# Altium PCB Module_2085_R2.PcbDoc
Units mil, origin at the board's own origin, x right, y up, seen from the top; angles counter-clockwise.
Board outline 6000 x 4000 mil, 2 copper layers (Top Layer, Bottom Layer); 61 components, 40 nets, 171 pads, 11 vias.
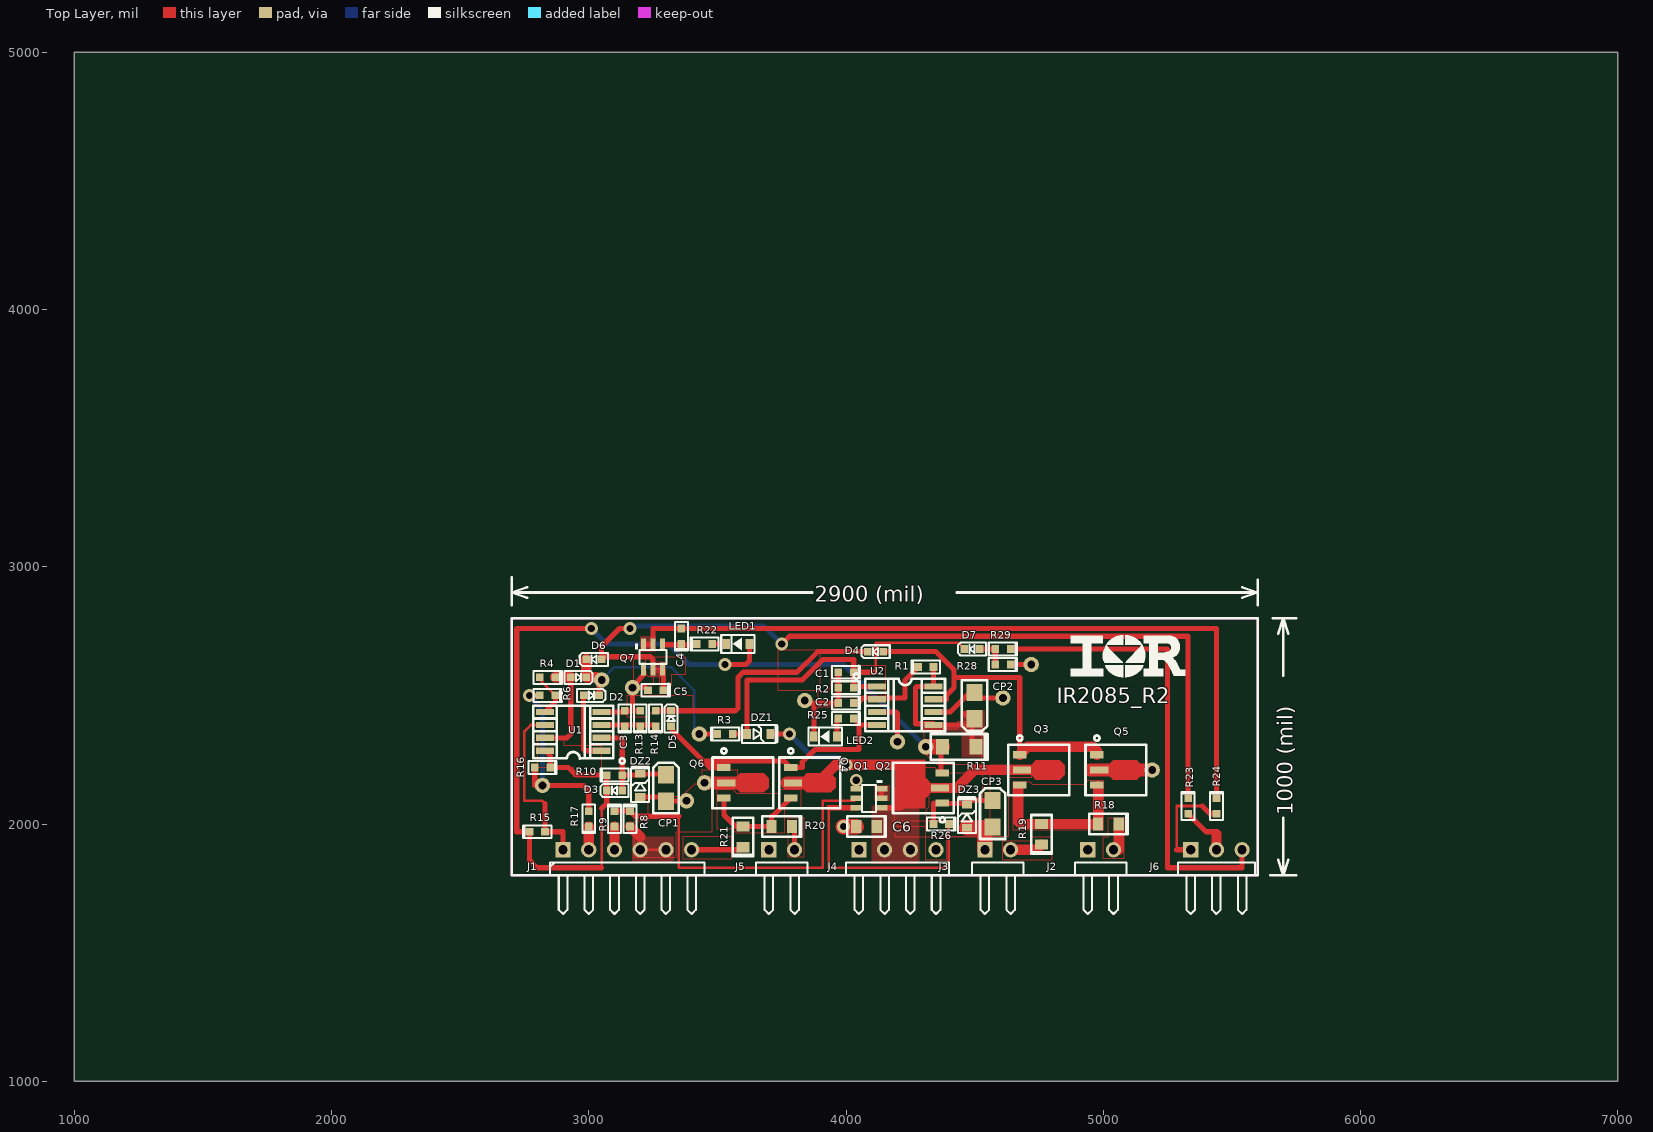
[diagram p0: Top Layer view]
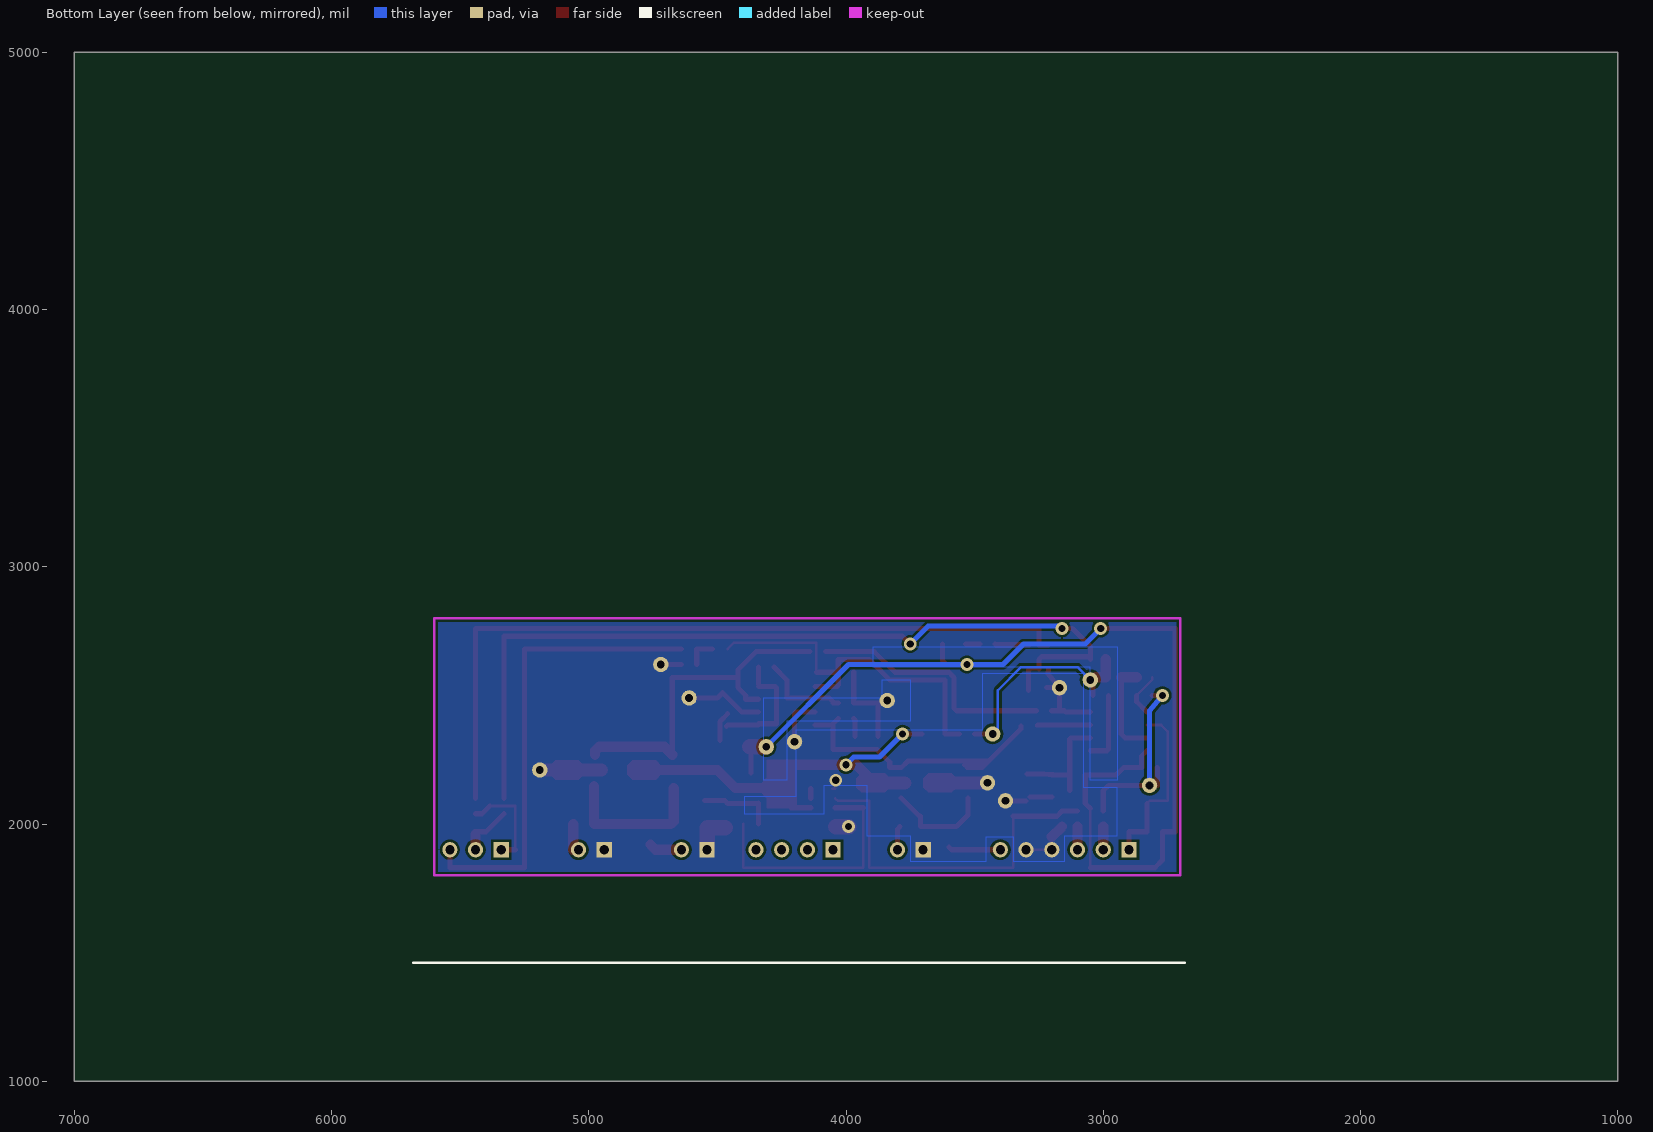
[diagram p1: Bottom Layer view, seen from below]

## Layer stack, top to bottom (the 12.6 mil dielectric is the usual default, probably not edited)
Top Layer: signal copper 1.4
Dielectric: dielectric 12.6, FR-4, Dk 4.8
Bottom Layer: signal copper 1.4

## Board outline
1000,1000 7000,1000 7000,5000 1000,5000

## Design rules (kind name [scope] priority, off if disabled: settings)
Clearance [All] p1: gap=10
ComponentClearance [All] p1: gap=10 collisioncheckmode=3 verticalgap=10
PlaneConnect [All] p1: planeconnectstyle=Direct reliefexpansion=20 reliefentries=4 reliefconductorwidth=10 reliefairgap=10
PolygonConnect [All] p1: connectstyle=Direct reliefconductorwidth=10 reliefentries=4 polygonreliefangle="90 Angle"
RoutingVias [All] p1: holewidth=28 width=40 viastyle="Through Hole" minholewidth=28 minwidth=38 maxholewidth=28 maxwidth=50
SolderMaskExpansion [All] p1: expansion=4
TestPointUsage [All] p1: valid=0 allowmultiple=FALSE
Testpoint [All] p1: side=15 testpointundercomponent=TRUE minsize=40 maxsize=100 preferedsize=60 minholesize=0 maxholesize=40 preferedholesize=32 testpointgrid=1 style=1023 order=0-112345678
Width [All] p1: maxlimit=40 minlimit=10 preferedwidth=20
17 further rules are at their usual default settings.

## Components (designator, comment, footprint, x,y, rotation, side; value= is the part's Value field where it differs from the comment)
C1 "C-603" C-603 4000,2590 r270 top
C2 "C-603" C-603 4000,2470 r270 top
C3 "C-603" C-603 3140,2410 r180 top
C4 "C-603" C-603 3360,2730 r180 top
C5 "C-603" C-603 3260,2520 r270 top
C6 "C-805" C-805 4080,1990 r270 top
CP1 "C-TAN-A" C-TAN-A 3300,2140 r0 top
CP2 "C-TAN-A" C-TAN-a 4500,2460 r180 top
CP3 "C-TAN-A" C-TAN-a 4570,2040 r0 top
D1 "SOD323_D" SOD523_D 2960,2570 r0 top
D2 "SOD323_D" SOD523_D 3010,2500 r0 top
D3 "SOD323_D" SOD523_D 3100,2130 r180 top
D4 "SOD323_D" SOD523_D 4115,2670 r180 top
D5 "SOD323_D" SOD523_D 3320,2410 r90 top
D6 "SOD323_D" SOD523_D 3020,2640 r180 top
D7 "SOD323_D" SOD523_D 4490,2680 r180 top
DZ1 "SOD123_Z" SOD323_Z 3660,2350 r180 top
DZ2 "SOD123_Z" SOD323_Z 3200,2150 r270 top
DZ3 "SOD123_Z" SOD323_Z 4470,2030 r270 top
J1 "Header 6H" HDR1X6H 2900,1900 r0 top locked
J2 "Header 2" HDR1X2H 4940,1900 r0 top
J3 "Header 2" HDR1X2H 4540,1900 r0 top
J4 "Header 4H" HDR1X4H 4050,1900 r0 top locked
J5 "Header 2" HDR1X2H 3700,1900 r0 top locked
J6 "Header 3H" HDR1X3H 5340,1900 r0 top
LED1 "LED-805" LED-805 3580,2700 r0 top
LED2 "LED-805" LED-805 3920,2340 r0 top
Q1 "XN4311" XN04311_XN04311(Primary) 4090,2100 r0 top
Q2 "PBSS305NX" SOT89 4320,2140 r90 top
Q3 "PBSS305NX" SOT89 4730,2210 r270 top
Q4 "PBSS305NX" SOT89 3840,2160 r270 top
Q5 "PBSS305PX" SOT89 5030,2210 r270 top
Q6 "PBSS305PX" SOT89 3580,2160 r270 top
Q7 "XN4311" XN04311_XN04311(Primary) 3250,2650 r90 top
R1 "R-603" R-603 4310,2610 r180 top
R2 "R-603" R-603 4000,2530 r0 top
R3 "R-603" R-603 3530,2350 r180 top
R4 "R-603" R-603 2840,2570 r0 top
R6 "R-603" R-603 2840,2500 r0 top
R8 "R-603" R-603 3160,2020 r90 top
R9 "R-603" R-603 3100,2020 r90 top
R10 "R-603" R-603 3100,2190 r180 top
R11 "R-1206" R-1206 4440,2300 r0 top
R13 "R-603" R-603 3200,2410 r270 top
R14 "R-603" R-603 3260,2410 r270 top
R15 "R-603" R-603 2800,1970 r180 top
R16 "R-603" R-603 2820,2220 r0 top
R17 "R-603" R-603 3000,2020 r270 top
R18 "R-805" R-805 5020,2000 r180 top
R19 "R-805" R-805 4760,1960 r90 top
R20 "R-805" R-805 3750,1990 r180 top
R21 "R-805" R-805 3600,1950 r90 top
R22 "R-603" R-603 3450,2700 r180 top
R23 "R-603" R-603 5330,2070 r90 top
R24 "R-603" R-603 5440,2070 r90 top
R25 "R-603" R-603 4000,2410 r0 top
R26 "R-603" R-603 4370,2000 r0 top
R28 "R-603" R-603 4610,2620 r0 top
R29 "R-603" R-603 4610,2680 r0 top
U1 "TLC082" SO8 2940,2360 r180 top
U2 "IR2086" SO8 4230,2460 r0 top

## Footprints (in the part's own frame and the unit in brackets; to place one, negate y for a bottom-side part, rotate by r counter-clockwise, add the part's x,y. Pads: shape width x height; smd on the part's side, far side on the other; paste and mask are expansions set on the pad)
C-603 [mil]
  rect 30x30 smd: 1(0,30) 2(0,-30)
  silkscreen extent -25,-55 25,55
C-805 [mil]
  rect 50x40 smd: 1(0,40) 2(0,-40)
  silkscreen extent -40,-75 40,75
C-TAN-A [mm]
  rect 1.6x1.7 smd: 1(0,1.3) 2(0,-1.3)
  silkscreen extent -1.25,-2.5 1.25,2.5
C-TAN-a [mm]
  rect 1.6x1.7 smd: 1(0,1.3) 2(0,-1.3)
  silkscreen extent -1.25,-2.5 1.25,2.5
HDR1X2H [mm] "Connector; Header; 2 Position; Right Angle"
  rect 1.5x1.5 hole 0.9: 1(0,0)
  round 1.5 hole 0.9: 2(2.54,0)
  silkscreen extent -1.27,-6.35 3.81,-1.27
HDR1X3H [mm] "Connector; Header; 3 Position; Right Angle"
  rect 1.5x1.5 hole 0.9: 1(0,0)
  round 1.5 hole 0.9: 2(2.54,0) 3(5.08,0)
  silkscreen extent -1.27,-6.35 6.35,-1.27
HDR1X4H [mm] "Connector; Header; 4 Position; Right Angle"
  rect 1.5x1.5 hole 0.9: 1(0,0)
  round 1.5 hole 0.9: 2(2.54,0) 3(5.08,0) 4(7.62,0)
  silkscreen extent -1.27,-6.35 8.89,-1.27
HDR1X6H [mm] "Connector; Header; 6 Position; Right Angle"
  rect 1.5x1.5 hole 0.9: 1(0,0)
  round 1.5 hole 0.9: 2(2.54,0) 3(5.08,0) 4(7.62,0) 5(10.16,0) 6(12.7,0)
  silkscreen extent -1.27,-6.35 13.97,-1.27
LED-805 [mil]
  rect 30x40 smd: 1(-45,0) 2(45,0)
  silkscreen extent -65,-35 65,35
R-603 [mil]
  rect 30x30 smd: 1(30,0) 2(-30,0)
  silkscreen extent -55,-25 55,25
R-805 [mil]
  rect 40x50 smd: 1(-40,0) 2(40,0)
  silkscreen extent -75,-40 75,40
R-1206 [mil]
  rect 50x60 smd: 1(65,0) 2(-65,0)
  silkscreen extent -110,-50 110,50
SO8 [mil]
  rect 70x24 smd: 1(-110,75) 2(-110,25) 3(-110,-25) 4(-110,-75) 5(110,-75) 6(110,-25) 7(110,25) 8(110,75)
  silkscreen extent -200,-100 155,125
SOD323_Z [mil]
  rect 30x40 smd: 1(-45,0) 2(45,0)
  silkscreen extent -70,-35 65,35
SOD523_D [mil]
  rect 30x30 smd: 1(30,0) 2(-30,0)
  silkscreen extent -55,-25 55,25
SOT89 [mm]
  rect 0.7x1.35 smd: 1(-1.5,-1.388) 3(1.5,-1.388)
  rect 0.7x1.8 smd: 2(0,-1.162)
  round 0 smd paste-25.4 mask-25.4: 4(0,1.388)
  Top Layer region: 0.475,3.037 0.95,2.562 0.95,0.213 0.475,-0.262 -0.475,-0.262 -0.95,0.213 -0.95,2.562 -0.475,3.037
  silkscreen extent -3.4,-2.51 2.5,3.49
XN04311_XN04311(Primary) [mil]
  rect 50x20 smd: 1(47,37) 2(47,0) 3(47,-37) 4(-48,-37) 5(-48,0) 6(-48,37)
  silkscreen extent -28,-53 50,70

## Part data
CP1 CP2 CP3: library part C-TAN-B, "C-TAN-B"
D7: "DIODE SWITCH 100V 150MW SOD-523"
DZ3: "DIODE ZENER 200MW 12V SOD323"
J1 J4 J6: library part "Header 2", "Header, 2-Pin"
J2 J3 J5: "Header, 2-Pin"
LED2: "LED 468NM BLUE CLEAR 0805 SMD"
Q2 Q3 Q4: library part SOT89-NPN, "SOT89-NPN"
Q5 Q6: library part SOT89-PNP, "SOT89-PNP"
R22: library part R-805, "R-805"
R25: "RES 4.7K OHM 1/10W 5% 0603 SMD"
R26 R28: "RES 1.0K OHM 1/10W 5% 0603 SMD"
R29: "RES 56K OHM 1/10W 5% 0603 SMD"
U1: library part LM833
U2: library part IR2085

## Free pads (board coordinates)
  round 60 hole 30: 4(2820,2150) 7(5190,2210) 9(3380,2090) 10(3450,2160) 11(3840,2480) 12(4200,2320) 13(4720,2620) 14(4610,2490) 15(3170,2530) 16(3050,2560) 18(4310,2300) 20(3430,2350)

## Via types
v1: diameter 50, hole 28, Top Layer to Bottom Layer, 11 vias

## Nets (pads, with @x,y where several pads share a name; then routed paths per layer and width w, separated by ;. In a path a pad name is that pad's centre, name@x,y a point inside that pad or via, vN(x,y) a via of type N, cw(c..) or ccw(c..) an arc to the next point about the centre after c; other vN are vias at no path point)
14.4V: DZ1.1 J4.2 J4.3 Q1.3 Q2.2 Q3.2 Q4.2 | length 1510.8
  Top Layer w20: DZ1.1 v1(3780,2350) ; Q1.3 4213,2063 4230,2080 4227,2083
  Top Layer w40: 3894.63,2164.63 3960,2230 4250,2230 ; 4250,2140 4290,2140 4430,2140 4500,2210 4750,2210
  Top Layer w50: Q4.2@3770,2160 3920.39,2160
  Bottom Layer w20: v1(3780,2350) 3870,2260 3970,2260 v1(4000,2230)
CS: C1.1 D7.1 DZ1.2 R2.1 R3.2 U2.1 | length 1458.5
  Top Layer w10: 4115,2590 4115,2705 4435,2705 D7.1
  Top Layer w20: R3.2 DZ1.2 3615,2557.93 ; 3615,2560 3830,2560 3910,2640 4030,2640 4030,2540 4035,2535 U2.1 ; C1.1 4115,2590
GND: C1.2 C2.2 C3.2 C5.2 C6.2 CP1.2 CP2.2 CP3.2 DZ2.2 DZ3.2 J1.4 J1.5 J2.1 J3.1 J5.1 LED2.1 pad.7 pad.9 pad.10 pad.11 pad.12 pad.13 pad.14 pad.15 Q1.6 Q5.2 Q6.2 Q7.6 R2.2 R8.2 R13.2 R28.1 U1.4 U2.3 U2.6 | length 2426.3
  Top Layer w10: 3200,1950 J1.4 J1.5 ; v1@4030,2160 4053,2137 Q1.6
  Top Layer w20: U1.4 3145,2435 3150,2440 R13.2 ; 3170,2440 pad.15 ; DZ2.2 CP1.2@3283.82,2105 ; Q7.6 3214.72,2584.35 pad.15 ; C5.2@3220,2530 pad.15 ; CP1.2 3301.18,2090 pad.9 ; pad.11 3850,2470 C2.2 C1.2 ; LED2.1 3875,2470 ; U2.3 4195,2435 4200,2430 pad.12 ; U2.6 4405,2435 CP2.2@4480,2510 ; CP2.2@4480,2511.18 CP2.2@4480,2510 ; pad.14 4500,2490 CP2.2@4480,2510 ; R28.1 pad.13
  Top Layer w40: R8.2 3200,1950
  Top Layer w50: pad.10 3670,2160 ; Q5.2@4950,2210 pad.7
  Top Layer w60: v1(3990,1990) C6.2 ; DZ3.2 4540,1985 J3.1
  other v1: 4040,2170
LO1: D5.2 Q4.1 Q6.1 R25.1 U2.4 | length 1220.5
  Top Layer w20: D5.2 3320,2370 3470,2220 Q6.1@3530,2220 ; 3450,2245.37 3759.06,2245.37 Q4.1 3830,2219.06 3830,2240 3880,2290 4050,2290 4050,2380 ; 3470,2240 3480,2230 Q6.1@3540,2230 ; 3500,2245.37 3502.69,2242.69 ; 3502.69,2241.74 Q6.1@3514.43,2230 ; Q6.1 Q6.1@3525.37,2220 ; R25.1 4055,2385 U2.4
NetC2_1: C2.1 R1.1 U2.2 | length 341.9
  Top Layer w20: C2.1 4050,2470 ; 4050,2475 4065,2490 4230,2490 4230,2555 ; 4230,2560 R1.1
NetC3_1: C3.1 R13.1 R14.1 U1.3 | length 212.1
  Top Layer w10: R14.1@3255,2385 R14.1
  Top Layer w20: U1.3 R14.1@3255,2385
NetC4_1: C4.1 Q7.3 R22.1 | length 134.2
  Top Layer w20: Q7.3 3417,2697 R22.1
NetCP1_1: CP1.1 D3.2 DZ2.1 R10.2 U1.2 | length 449
  Top Layer w20: U1.2 3125,2335 3130,2330 R10.2 ; D3.2 R10.2 ; CP1.1@3296.18,2195 3230,2195 3200.38,2191.66 3196.18,2191.18 3195,2190 R10.2
NetCP3_1: CP3.1 DZ3.1 Q2.1 R26.2 | length 310
  Top Layer w20: R26.2 4340,2080.78 Q2.1@4374.61,2080.23 ; Q2.1@4360,2080 4374.64,2080.23 4460.23,2080.23 4471.18,2091.18 CP3.1@4550,2091.18
NetD1_1: D1.1 D2.1 D6.1 pad.16 pad.20 R3.1 | length 850.4
  Top Layer w10: pad.16@3030,2570 pad.16@3040,2560
  Top Layer w20: D2.1 pad.16@3040,2560 ; v1(3430,2350) R3.1
  Top Layer w40: D6.1 D1.1 pad.16@3030,2570
  Bottom Layer w10: pad.16 3100,2610 3320,2610 3410,2520 3410,2370 v1(3430,2350)
NetD1_2: D1.2 R4.1 U1.7 | length 386.2
  Top Layer w20: U1.7 2915,2335 2930,2350 D1.2
  Top Layer w40: R4.1 D1.2
NetD2_2: D2.2 U1.1 | length 282.1
  Top Layer w10: 2980,2290 2985,2285
  Top Layer w20: 2980,2290 D2.2 ; 2985,2285 U1.1
NetD4_1: D4.1 D5.1 R14.2 | length 985.6
  Top Layer w20: R14.2 D5.1 3570,2440 3580,2450 3580,2570 3600,2590 3810,2590 3890,2670 D4.1@4080,2670
NetD4_2: D4.2 Q3.1 Q5.1 U2.7 | length 1377.5
  Top Layer w20: D4.2@4140,2670 4350,2670 4420,2600 4420,2570 ; U2.7 4390,2485 4390,2500 4420,2530 4420,2570 ; Q3.1 4675.37,2570 4420,2570
  Top Layer w40: Q3.1 4706.32,2300 4960,2300 4975.37,2284.63 Q5.1
NetJ1_1: J1.1 R15.2 U1.6 | length 694.5
  Top Layer w10: 2830,2080 2820,2090 2750,2090 2750,2360 2775,2385 U1.6
  Top Layer w20: 2830,2080 R15.2 2900,1970 J1.1
NetJ1_2: J1.2 R17.1 | length 90
  Top Layer w40: J1.2 R17.1
NetJ1_6: J1.6 R21.1 | length 204.1
  Top Layer w20: J1.6 3590,1900 R21.1
NetJ2_2: J2.2 R18.1 | length 120
  Top Layer w40: J2.2 5060,1900 R18.1
NetJ3_2: J3.2 R19.1 | length 138.3
  Top Layer w40: J3.2@4630,1900 4740,1900 R19.1
NetJ5_2: J5.2 R20.1 | length 94.1
  Top Layer w20: R20.1 3800,1980 J5.2
NetJ6_1: J6.1 R24.2 | length 392.4
  Top Layer w10: 5285,1900 5285,2070 5385,2070
  Top Layer w20: 5285,1900 J6.1 ; 5385,2070 5415,2040 R24.2
NetJ6_2: J6.2 R23.2 | length 203.1
  Top Layer w20: R23.2 5400,1970 5430,1970 5440,1960
  Top Layer w40: J6.2 5440,1960
NetJ6_3: J6.3 R29.1 | length 1820
  Top Layer w20: R29.1 5250,2680 5250,1830 5540,1830 J6.3
NetLED1_1: LED1.1 R22.2 | length 55
  Top Layer w20: R22.2 LED1.1
NetLED2_2: LED2.2 R25.2 | length 72.1
  Top Layer w20: LED2.2 3965,2405 R25.2
NetQ1_1: Q1.1 Q1.2 | length 37
  Top Layer w20: Q1.2 Q1.1
NetQ1_4: Q1.4 R26.1 | length 979
  Top Layer w10: 3933,2063 3933,1830 4400,1830 R26.1
  Top Layer w20: 3933,2063 Q1.4
NetQ1_5: Q1.5 R8.1 R9.1 | length 1414.4
  Top Layer w10: 3350,2030 3350,1830 3910,1830 3910,2090 4032,2090 Q1.5
  Top Layer w20: R9.1 R8.1 3180,2030 3350,2030
NetQ3_3: Q3.3 Q5.3 R18.2 R19.2 | length 590.5
  Top Layer w40: Q3.3@4670,2140 4670,2010 4680,2000 R18.2 Q5.3@4980,2146.32
NetQ4_3: Q4.3 Q6.3 R20.2 R21.2 | length 414.2
  Top Layer w20: Q6.3 3525.37,2034.63 3570,1990 R20.2 3710,2030 3714.43,2030 Q4.3
NetR4_2: R4.2 R6.1 U1.5 | length 176.4
  Top Layer w10: R4.2 2810,2560 R6.1
  Top Layer w20: U1.5 2870,2475 R6.1
NetR6_2: pad.4 R6.2 R16.2 R17.2 | length 776.4
  Top Layer w20: v1(2770,2500) R6.2 ; R16.2 2790,2150 2980,2150 3000,2130 R17.2
  Bottom Layer w20: v1(2770,2500) 2820,2440 pad.4
OVP2: D7.2 R28.2 R29.2 | length 120
  Top Layer w20: D7.2 R29.2 R28.2
"REMOTE ON": J1.3 R9.2 | length 90
  Top Layer w40: J1.3 R9.2
SCP+: C5.1 D6.2 Q7.4 Q7.5 R23.1 | length 3396.9
  Top Layer w10: Q7.5 Q7.4
  Top Layer w20: D6.2 3050,2690 3120,2760 v1(3160,2760) ; D6.2@3050,2650 3240,2650 3250,2640 Q7.5 ; Q7.4 3290,2599 C5.1 ; v1(3750,2700) 3780,2730 5330,2730 R23.1
  Bottom Layer w20: v1(3160,2760) 3170,2770 3680,2770 v1(3750,2700)
SCP-: C4.2 Q7.1 Q7.2 R24.1 | length 2950
  Top Layer w20: Q7.1 Q7.2 3250,2760 C4.2 5440,2760 R24.1
TURN_ON: D3.1 LED1.2 pad.18 Q2.3 R10.1 R11.2 R15.1 R16.1 U1.8 | length 4029.1
  Top Layer w10: 3050,1830 3050,2060
  Top Layer w20: U1.8 2850,2265 R16.1 2920,2220 2950,2190 R10.1 D3.1 3070,2080 3050,2060 ; v1(3010,2760) 2720,2760 2720,1970 R15.1 2770,1860 2800,1830 3050,1830 ; v1(3530,2620) 3610,2620 3625,2635 LED1.2 ; Q2.3@4370,2199.06 R11.2@4370,2300
  Top Layer w60: v1(4310,2300) R11.2
  Bottom Layer w20: v1(3010,2760) 3070,2700 3310,2700 3390,2620 3990,2620 v1(4310,2300)
VCC: CP2.1 R1.2 R11.1 U2.5 U2.8 | length 595.4
  Top Layer w20: U2.8 4275,2535 4270,2530 4270,2390 4340,2390 U2.5 4460,2385 4465,2380 ; U2.8@4340,2545 R1.2 ; 4460,2428.82 4490,2398.82 R11.1@4490,2325
VS1: J4.1
VS2: J4.4
pads on no net: C6.1 Q2.4 Q3.4 Q4.4 Q5.4 Q6.4

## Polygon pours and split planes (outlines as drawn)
VCC on Top Layer "Top Layer-VCC 1" (solid, pour order 1006): 4450,2440 4450,2390 4300,2390 4300,2360 4450,2360 4450,2260 4540,2260 4540,2440
14.4V on Top Layer "Top Layer-14.4V 2" (solid, pour order 1005): 4110,2070 4111.52,2071.52 4221.52,2071.52 4221.52,2031.52 4220,2030 4110,2030
GND on Top Layer "Top Layer-GND 3" (solid, pour order 1003): 3170,1950 3170,1850 3320,1850 3330,1860 3330,1950
SCP+ on Top Layer "Top Layer-SCP+ 1" (solid, pour order 1002): 3240,2630 3300,2630 3300,2570 3240,2570
SCP- on Top Layer "Top Layer-SCP-" (solid, pour order 1001): 3200,2730 3260,2730 3260,2670 3200,2670
NetQ1_1 on Top Layer "Top Layer-NetQ1_1" (solid, pour order 1000): 4110,2150 4110,2090 4170,2090 4170,2150
14.4V on Top Layer "Top Layer-14.4V" (solid, pour order 1004): 4285,1845 4284.67,1935 4284.67,2235 4210,2235 4210,2070 4100,2070 4100,1845
GND on Bottom Layer "Bottom Layer-GND" (solid, pour order 1007): 2710,2790 2710,1810 5590,1810 5590,2790
GND on Bottom Layer "Bottom Layer-GND 1" (solid, shelved, pour order 1010): 3075,2585 3470,2585 3470,2365 4195,2365 4195,2105 4395,2105 4395,2040 4085,2040 4085,2150 3920,2150 3920,1955 3750,1955 3750,1855 3455,1855 3455,1950 3350,1950 3350,1855 3150,1855 3150,1955 2945,1955 2945,2140 3075,2140
TURN_ON on Bottom Layer "Bottom Layer-TURN_ON" (solid, shelved, pour order 1007): 3895,2690 2945,2690 2945,2170 3050,2170 3050,2610 3895,2610
TURN_ON on Bottom Layer (solid, shelved): 4230,2170 4320,2170 4320,2490 3860,2490 3860,2560 3750,2560 3750,2400 4230,2400
GND on Top Layer "Top Layer-GND 1" (solid, shelved, pour order 1008): 3175,2010 3175,1870 3340,1870 3340,1970 3480,1970 3480,2150 3481.95,2151.95 3579.02,2151.95 3579.02,2208.05 3441.95,2208.05 3440,2210 3440,2155 3410,2155 3360,2105 3235,2105 3230,2100 3230,2010
GND on Top Layer "Top Layer-GND" (solid, shelved, pour order 1007): 3150,2500 3405,2500 3405,2440 3250,2440 3225,2415 3150,2415
NetJ2_2 on Top Layer "Top Layer-NetJ2_2" (solid, shelved, pour order 1006): 5020,2025 5080,2025 5080,1865 5000,1865 5000,1950 5020,1950
NetJ3_2 on Top Layer "Top Layer-NetJ3_2" (solid, shelved, pour order 1005): 4610,1935 4720,1935 4720,1950 4800,1950 4800,1860 4610,1860
NetJ5_2 on Top Layer "Top Layer-NetJ5_2" (solid, shelved, pour order 1004): 3775,2025 3835,2025 3835,1870 3775,1870
NetJ1_6 on Top Layer "Top Layer-NetJ1_6" (solid, shelved, pour order 1003): 3555,1950 3365,1950 3365,1865 3555,1865
NetQ3_3 on Top Layer "Top Layer-NetQ3_3" (solid, shelved, pour order 1002): 4650,2165 4715,2165 4725,2155 4935,2155 4935,2165 4940,2170 5000,2170 5000,1975 4650,1975
NetQ4_3 on Top Layer "Top Layer-NetQ4_3" (solid, shelved, pour order 1001): 3500,2135 3560,2135 3575,2120 3740,2120 3740,2135 3825,2135 3825,2060 3760,2060 3760,1965 3575,1965 3560,1980 3500,1980
CS on Top Layer "Top Layer-CS" (solid, shelved, pour order 1000): 4155,2615 3940,2615 3940,2530 3925,2515 3890,2515 3890,2450 3895,2455 3960,2455 3960,2485 3970,2495 4155,2495
14.4V on Top Layer "Top Layer-14.4V 1" (solid, shelved, pour order 1001): 4310,2010 4560,2010 4560,2230 4718.37,2230 4719.67,2228.7 4719.67,2180.33 4720,2180 4630,2180 4630,1950 4390,1950 4390,1860 4310,1860
TURN_ON on Top Layer "Top Layer-NetQ2_3" (solid, shelved, pour order 1002): 4220,2220 4345,2220 4365,2200 4530,2200 4530,2100 4440,2100 4440,2140 4340,2140 4330,2150 4220,2150
VCC on Top Layer "Top Layer-VCC" (solid, shelved, pour order 1003): 4305,2370 4435,2370 4435,2400 4525,2400 4525,2230 4355,2230 4305,2275
TURN_ON on Top Layer "Top Layer-TURN_ON" (solid, shelved, pour order 1005): 3050,2185 3050,2305 2905,2305 2905,2330 2800,2330 2800,2220 2940,2220 2940,2185
GND on Top Layer "Top Layer-GND 2" (solid, shelved, pour order 1000): 3175,2650 3220,2650 3220,2585 3230,2575 3250,2575 3250,2540 3175,2540
SCP+ on Top Layer "Top Layer-SCP+" (solid, shelved, pour order 1001): 3245,2650 3375,2650 3375,2580 3320,2580 3320,2540 3275,2540 3275,2590 3245,2590
14.4V on Top Layer (solid, shelved): 4560,2010 4180,2010 4190,2000 4190,1950 4560,1950
14.4V on Top Layer (solid, shelved): 4190.48,1990 4190.48,2140 4309.52,2140 4320.81,2125.88 4320.81,2065.42 4310.48,2052.5 4310.48,1990
TURN_ON on Top Layer (solid, shelved): 3735,2520 3900,2520 3900,2675 3735,2675

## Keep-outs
Keep-Out Layer:
  lines w10: 2700,1800 2700,2800 5600,2800 5600,1800 2700,1800

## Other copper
Top Layer:
  rectangle net 14.4V: 4190,2060 4310,2250

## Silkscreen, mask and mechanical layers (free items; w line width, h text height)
Top Overlay:
  drawing of 387 lines, arcs and shapes, not listed
  text "2900 (mil)" at 3879.09,2864.01 h60
  text "IR2085_R2" at 4820,2470 h60
  text "1000 (mil)" at 5735.99,2034.08 h60 r90
Bottom Overlay:
  lines w10: 2682.88,1460 5682.88,1460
